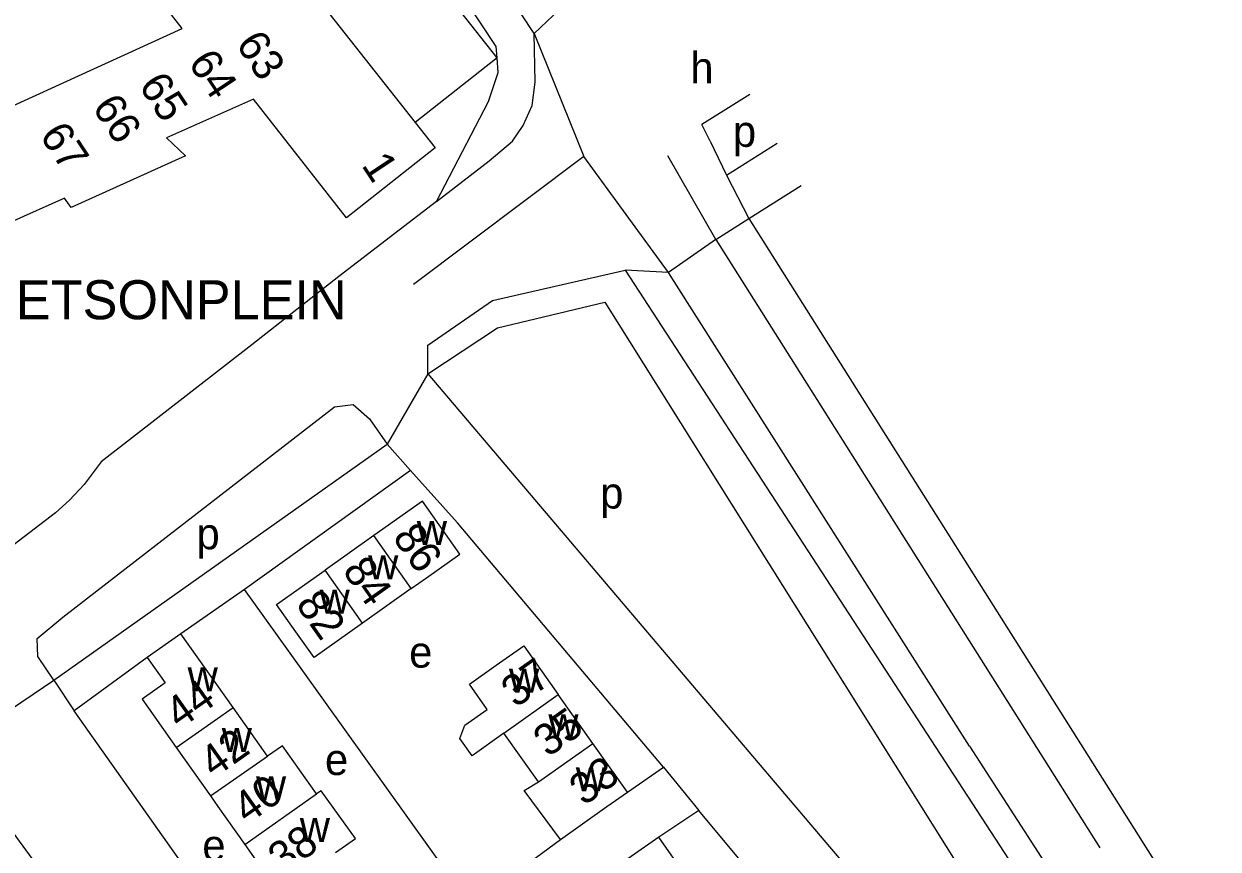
# Model space of a CAD drawing. Extents: x 158848 to 160613, y 385889 to 387762.
# Drawn here: x 160280.6 to 160433.5, y 386744.6 to 386850.2 of the extents above; entities that cross this region are included whole.
import ezdxf

# ---------------------------------------------------------------- set-up
doc = ezdxf.new("R2010")
doc.units = 0
for name, color, linetype in [('BLT_Basislijn', 7, 'Continuous'), ('BLT_Bebouwing', 7, 'Continuous'), ('BLT_Centroide', 7, 'Continuous'), ('BLT_Huisnummer', 7, 'Continuous'), ('BLT_Huisnummer_ tussenligend', 7, 'Continuous'), ('BLT_Huisnummer_reeks', 7, 'Continuous'), ('BLT_Onderverdeling_panden', 7, 'Continuous'), ('BLT_Straatnaam', 7, 'Continuous'), ('BLT_Vlakafsluiter', 7, 'Continuous')]:
    doc.layers.add(name, color=color, linetype=linetype)

msp = doc.modelspace()

# ---------------------------------------------------------------- linework, layer by layer
at = {"layer": 'BLT_Basislijn'}
for p, q in [((160341.16, 386845.85), (160306.29, 386890.22)), ((160341.16, 386845.85), (160330.67, 386837.59)), ((160368.44, 386835.19), (160367.4, 386837.32)), ((160370.56, 386830.84), (160377.05, 386834.92)), ((160352.29, 386833.22), (160330.45, 386816.83)), ((160369.18, 386822.6), (160363.04, 386833.3)), ((160370.56, 386830.84), (160373.41, 386825.27)), ((160373.41, 386825.27), (160433.49, 386730.11)), ((160369.18, 386822.6), (160418.35, 386744.72)), ((160363.85, 386817.2), (160363.12, 386818.35)), ((160284.41, 386766.17), (160327.09, 386796.4)), ((160327.09, 386796.4), (160330.07, 386793.04)), ((160330.07, 386793.04), (160308.81, 386777.78)), ((160308.81, 386777.78), (160300.69, 386772.13)), ((160296.38, 386769.09), (160287.01, 386762.27)), ((160284.41, 386766.17), (160287.01, 386762.27)), ((160315.59, 386721.93), (160287.01, 386762.27)), ((160271.82, 386756.68), (160294.41, 386725.95)), ((160357.85, 386751.85), (160362.48, 386755.03)), ((160362.48, 386755.03), (160367.01, 386749.49)), ((160367.01, 386749.49), (160361.86, 386746.09)), ((160337.79, 386737.32), (160349.27, 386745.78))]:
    msp.add_line(p, q, dxfattribs=at)
for points in [[(160345.92, 386848.96), (160321.89, 386885.38), (160315.52, 386895.7)], [(160341.16, 386845.85), (160341.04, 386847.28), (160317.68, 386882.69), (160312.04, 386891.83)], [(160343.13, 386835.16), (160344.5, 386837.18), (160345.66, 386839.74), (160346.05, 386842.74), (160345.92, 386848.96)], [(160340.06, 386840.26), (160341.31, 386843.97), (160341.16, 386845.85)], [(160333.42, 386827.47), (160340.06, 386840.26)], [(160373.51, 386841.17), (160367.4, 386837.32)], [(160333.42, 386827.47), (160340.15, 386832.65), (160343.13, 386835.16)], [(160368.44, 386835.19), (160370.56, 386830.84)], [(160373.41, 386825.27), (160380.12, 386829.52)], [(160333.42, 386827.47), (160320.92, 386817.85), (160309.78, 386809.1), (160290.48, 386794.11)], [(160332.3, 386805.38), (160332.3, 386809.06), (160340.6, 386814.78), (160357.58, 386818.68)], [(160363.12, 386818.35), (160357.58, 386818.68)], [(160357.58, 386818.68), (160409.58, 386738.73), (160425.46, 386716.58)], [(160401.65, 386757.71), (160363.85, 386817.2)], [(160332.3, 386805.38), (160341.21, 386811.28), (160354.98, 386814.58), (160416.45, 386716.52), (160416.9, 386714.44), (160416.93, 386712.38), (160414.52, 386708.62)], [(160332.3, 386805.38), (160414.52, 386708.62)], [(160284.41, 386766.17), (160282.37, 386769.22), (160282.29, 386771.53), (160285.55, 386774.24), (160320.36, 386801.15), (160322.75, 386801.47), (160324.84, 386799.65), (160327.09, 386796.4)], [(160290.48, 386794.11), (160288.29, 386791.23), (160286.43, 386789.22), (160284.64, 386787.62), (160279.32, 386783.55), (160278.5, 386783.02), (160277.43, 386782.58), (160276.23, 386782.36), (160274.94, 386782.4), (160273.73, 386782.71), (160272.75, 386783.14), (160271.94, 386783.74), (160271.25, 386784.44), (160266.19, 386791.63)], [(160362.48, 386755.03), (160336.11, 386786.33), (160330.07, 386793.04)], [(160337.79, 386737.32), (160316.29, 386767.38), (160311.2, 386774.46), (160308.81, 386777.78)], [(160401.65, 386757.71), (160412.15, 386741.49), (160425.02, 386724.79)], [(160419.96, 386682.62), (160419.42, 386683.49), (160412.39, 386694.53), (160408.97, 386699.1), (160367.01, 386749.49)]]:
    msp.add_lwpolyline(points, dxfattribs=at)
at = {"layer": 'BLT_Bebouwing'}
for p, q in [((160325.38, 386784.68), (160319.15, 386780.28)), ((160330.17, 386777.9), (160323.95, 386773.49)), ((160300.69, 386772.13), (160296.38, 386769.09)), ((160307.36, 386762.68), (160300.69, 386772.13)), ((160353.43, 386758.09), (160349.01, 386764.34)), ((160311.77, 386756.43), (160307.36, 386762.68)), ((160346.46, 386753.16), (160342.04, 386759.41)), ((160300.1, 386757.55), (160304.48, 386751.35)), ((160357.85, 386751.85), (160353.43, 386758.09)), ((160308.86, 386745.14), (160313.25, 386738.93)), ((160361.86, 386746.09), (160354.7, 386741.07)), ((160366.22, 386739.92), (160361.86, 386746.09))]:
    msp.add_line(p, q, dxfattribs=at)
for points in [[(160310.03, 386863.78), (160330.67, 386837.59), (160333.24, 386834.33)], [(160309.97, 386840.55), (160298.85, 386835.59), (160301.29, 386833.31), (160286.63, 386826.7), (160285.77, 386827.9), (160258.27, 386815.6), (160257.37, 386816.84), (160238.05, 386844.21)], [(160333.24, 386834.33), (160321.87, 386825.38), (160309.97, 386840.55)], [(160330.17, 386777.9), (160332.15, 386779.29), (160336.4, 386782.3), (160331.6, 386789.08), (160325.38, 386784.68)], [(160323.95, 386773.49), (160317.73, 386769.09), (160315.41, 386772.37), (160312.93, 386775.88), (160319.15, 386780.28)], [(160342.04, 386759.41), (160337.97, 386756.48), (160336.38, 386758.72), (160337.05, 386760.41), (160339.91, 386762.43), (160337.63, 386765.66), (160341.06, 386768.09), (160344.6, 386770.59), (160349.01, 386764.34)], [(160296.38, 386769.09), (160298.67, 386765.85), (160295.72, 386763.76), (160300.1, 386757.55)], [(160318.05, 386751.62), (160313.71, 386757.76), (160311.77, 386756.43)], [(160349.27, 386745.78), (160344.64, 386752.05), (160346.46, 386753.16)], [(160304.48, 386751.35), (160305.43, 386750), (160308.86, 386745.14)], [(160320.48, 386744.1), (160323.03, 386745.89), (160318.63, 386752.03), (160318.05, 386751.62)], [(160349.27, 386745.78), (160355.23, 386750), (160357.85, 386751.85)]]:
    msp.add_lwpolyline(points, dxfattribs=at)
msp.add_lwpolyline([(160244.56, 386848.67), (160257.55, 386829.86), (160300.86, 386849.59), (160291.65, 386861.46)], close=True, dxfattribs=at)
at = {"layer": 'BLT_Onderverdeling_panden'}
for p, q in [((160330.17, 386777.9), (160325.38, 386784.68)), ((160323.95, 386773.49), (160319.15, 386780.28)), ((160342.04, 386759.41), (160349.01, 386764.34)), ((160300.1, 386757.55), (160307.36, 386762.68)), ((160346.46, 386753.16), (160353.43, 386758.09)), ((160304.48, 386751.35), (160311.77, 386756.43)), ((160308.86, 386745.14), (160318.05, 386751.62))]:
    msp.add_line(p, q, dxfattribs=at)
at = {"layer": 'BLT_Vlakafsluiter'}
for p, q in [((160345.92, 386848.96), (160352.26, 386854.99)), ((160345.92, 386848.96), (160352.29, 386833.22)), ((160363.12, 386818.35), (160352.29, 386833.22)), ((160369.18, 386822.6), (160373.41, 386825.27)), ((160369.18, 386822.6), (160363.12, 386818.35)), ((160332.3, 386805.38), (160327.09, 386796.4)), ((160277.67, 386761.63), (160284.41, 386766.17))]:
    msp.add_line(p, q, dxfattribs=at)

# ---------------------------------------------------------------- texts
at = {"layer": 'BLT_Centroide'}
for s, p in [('h', (160365.91, 386842.59)), ('p', (160371.36, 386834.45)), ('p', (160354.37, 386788.15)), ('w', (160330.89, 386783.48)), ('p', (160302.68, 386782.93)), ('w', (160324.66, 386779.09)), ('w', (160318.44, 386774.69)), ('e', (160329.91, 386767.78)), ('w', (160301.55, 386764.75)), ('w', (160342.7, 386764.56)), ('w', (160347.73, 386758.75)), ('w', (160305.92, 386757)), ('e', (160319.13, 386754.03)), ('w', (160351.25, 386751.94)), ('w', (160310.3, 386750.81)), ('w', (160315.91, 386745.47)), ('e', (160303.43, 386743.04))]:
    msp.add_text(s, height=4, dxfattribs=at).set_placement(p)
at = {"layer": 'BLT_Huisnummer'}
for s, rotation, p in [('86', 305.266, (160327.68, 386784.46)), ('82', 305.2738, (160315.29, 386775.89)), ('37', 35.2569, (160343.55, 386762.55)), ('44', 35.2148, (160300.51, 386759.82)), ('33', 35.2681, (160352.27, 386750.01)), ('38', 35.2201, (160313.69, 386741.23))]:
    msp.add_text(s, height=4, rotation=rotation, dxfattribs=at).set_placement(p)
at = {"layer": 'BLT_Huisnummer_ tussenligend'}
for s, rotation, p in [('84', 305.2738, (160321.27, 386780.19)), ('35', 35.2681, (160347.67, 386756.22)), ('42', 35.2201, (160304.92, 386753.55)), ('40', 35.2201, (160309.19, 386747.65))]:
    msp.add_text(s, height=4, rotation=rotation, dxfattribs=at).set_placement(p)
at = {"layer": 'BLT_Huisnummer_reeks'}
for s, p in [('63', (160307.64, 386847.61)), ('64', (160301.53, 386845.21)), ('65', (160295.2, 386842.28)), ('66', (160289.24, 386839.51)), ('67', (160282.51, 386835.91)), ('1', (160323.73, 386832.09))]:
    msp.add_text(s, height=4, rotation=303.5058, dxfattribs=at).set_placement(p)
at = {"layer": 'BLT_Straatnaam'}
msp.add_text('GERRETSONPLEIN', height=5, dxfattribs=at).set_placement((160260.24, 386812.38))

doc.saveas('drawing.dxf')
